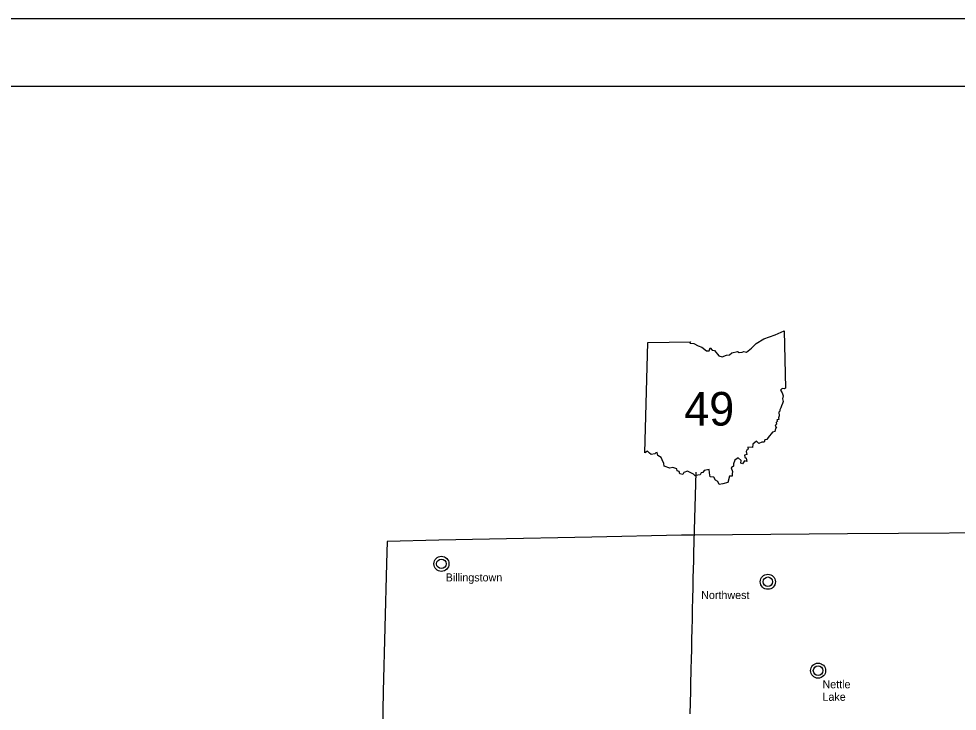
# Model space of a CAD drawing. Extents: x -66 to 795, y 0 to 440.
# Drawn here: x 111.4 to 250.6, y 337.3 to 440 of the extents above; entities that cross this region are included whole.
import ezdxf

# ---------------------------------------------------------------- set-up
doc = ezdxf.new("R2010")
doc.units = 0
for name, color, linetype in [('DV_X_Corp_Line', 7, 'Continuous'), ('GM_X_County', 7, 'Continuous'), ('GM_X_State_Route', 7, 'Continuous'), ('PV_P_Text', 7, 'Continuous'), ('SH_Border', 7, 'Continuous'), ('SH_Cut_Line', 7, 'Continuous')]:
    doc.layers.add(name, color=color, linetype=linetype)

msp = doc.modelspace()

# ---------------------------------------------------------------- linework, layer by layer
at = {"layer": 'DV_X_Corp_Line'}
for centre, radius in [((174.08, 359.17), 1.12), ((174.08, 359.17), 0.71), ((222.51, 356.51), 1.12), ((222.51, 356.51), 0.71), ((229.96, 343.33), 1.12), ((229.96, 343.33), 0.71)]:
    msp.add_circle(centre, radius, dxfattribs=at)
at = {"layer": 'GM_X_County'}
msp.add_lwpolyline([(256.96, 363.76), (241.88, 363.65), (234.32, 363.6), (211.6, 363.44), (209.69, 363.42), (196.42, 363.14), (181.24, 362.82), (173.68, 362.66), (166.04, 362.5), (165.94, 359.23), (165.44, 340.23), (165.03, 317.58)], dxfattribs=at)
at = {"layer": 'GM_X_State_Route'}
msp.add_lwpolyline([(210.98, 336.94), (211.03, 338.54), (211.07, 340.3), (211.09, 341.88), (211.11, 342.92), (211.14, 343.59), (211.18, 344.97), (211.21, 346.53), (211.24, 347.98), (211.28, 349.42), (211.31, 351.01), (211.35, 352.45), (211.38, 354.02), (211.42, 355.67), (211.45, 356.99), (211.48, 358.43), (211.49, 358.63), (211.51, 359.39), (211.54, 360.82), (211.57, 362.43), (211.85, 372.76)], dxfattribs=at)
at = {"layer": 'PV_P_Text'}
msp.add_line((204.24, 375.62), (204.7, 391.99), dxfattribs=at)
msp.add_line((204.24, 375.62), (204.7, 391.99), dxfattribs=at)
for points in [[(204.7, 391.99), (211.05, 392.1), (210.95, 391.9), (211.55, 391.86), (212.19, 391.51), (212.73, 391.29), (213.39, 390.77), (213.78, 390.77), (213.95, 391.2), (214.25, 390.87), (214.61, 390.81), (215.23, 390.03), (215.74, 389.86), (216.35, 390.13), (216.81, 390.17), (217.14, 390.44), (218.01, 390.66), (218.26, 390.53), (218.72, 390.55), (218.95, 390.65), (219.35, 390.56), (220.06, 391.16), (220.79, 391.86), (221.91, 392.52), (223.59, 393.15), (224.91, 393.71), (225.11, 385.22)], [(204.7, 391.99), (211.05, 392.1), (210.95, 391.9), (211.55, 391.86), (212.19, 391.51), (212.73, 391.29), (213.39, 390.77), (213.78, 390.77), (213.95, 391.2), (214.25, 390.87), (214.61, 390.81), (215.23, 390.03), (215.74, 389.86), (216.35, 390.13), (216.81, 390.17), (217.14, 390.44), (218.01, 390.66), (218.26, 390.53), (218.72, 390.55), (218.95, 390.65), (219.35, 390.56), (220.06, 391.16), (220.79, 391.86), (221.91, 392.52), (223.59, 393.15), (224.91, 393.71), (225.11, 385.22)], [(225.11, 385.22), (224.91, 385.1), (224.61, 385.15), (224.4, 384.91), (224.65, 384.52), (224.77, 384.1), (224.67, 383.63), (224.77, 383.25), (224.7, 382.93), (224.51, 382.61), (224.44, 382.31), (224.28, 381.99), (224.29, 381.81), (224.14, 381.67), (224.17, 381.14), (224.09, 380.84), (224.12, 380.59), (223.86, 380.52), (223.92, 380.31), (223.76, 380.15), (223.8, 379.87), (223.61, 379.7), (223.79, 379.34), (223.65, 379.23), (223.53, 378.79), (223.21, 378.7), (222.56, 377.91), (222.34, 377.61), (222.08, 377.54), (221.94, 377.23), (221.62, 377.23), (221.15, 377.01), (220.84, 377.38), (220.3, 376.94), (220.23, 376.43), (219.55, 376.45), (219.58, 376.19), (219.43, 376.11), (219.29, 375.85), (219.37, 375.39), (219.05, 375.28), (219.09, 375.01), (219.29, 374.85), (219.38, 374.34), (219.04, 374.44), (218.76, 374.01), (218.48, 374.11), (218.57, 374.48), (218.09, 374.91), (217.63, 374.56), (217.39, 374), (217.39, 373.63), (217.05, 373.4), (217.26, 372.87), (217.22, 372.5), (217.23, 372.15), (216.8, 372.16), (216.55, 371.22)], [(225.11, 385.22), (224.91, 385.1), (224.61, 385.15), (224.4, 384.91), (224.65, 384.52), (224.77, 384.1), (224.67, 383.63), (224.77, 383.25), (224.7, 382.93), (224.51, 382.61), (224.44, 382.31), (224.28, 381.99), (224.29, 381.81), (224.14, 381.67), (224.17, 381.14), (224.09, 380.84), (224.12, 380.59), (223.86, 380.52), (223.92, 380.31), (223.76, 380.15), (223.8, 379.87), (223.61, 379.7), (223.79, 379.34), (223.65, 379.23), (223.53, 378.79), (223.21, 378.7), (222.56, 377.91), (222.34, 377.61), (222.08, 377.54), (221.94, 377.23), (221.62, 377.23), (221.15, 377.01), (220.84, 377.38), (220.3, 376.94), (220.23, 376.43), (219.55, 376.45), (219.58, 376.19), (219.43, 376.11), (219.29, 375.85), (219.37, 375.39), (219.05, 375.28), (219.09, 375.01), (219.29, 374.85), (219.38, 374.34), (219.04, 374.44), (218.76, 374.01), (218.48, 374.11), (218.57, 374.48), (218.09, 374.91), (217.63, 374.56), (217.39, 374), (217.39, 373.63), (217.05, 373.4), (217.26, 372.87), (217.22, 372.5), (217.23, 372.15), (216.8, 372.16), (216.55, 371.22)], [(216.55, 371.22), (215.81, 371.04), (215.29, 370.94), (215.11, 371.36), (214.74, 371.59), (214.5, 372.02), (213.97, 372.08), (213.85, 372.67), (213.79, 373.15), (213.07, 373.03), (212.87, 372.73), (212.61, 372.66), (212.46, 372.36), (212.11, 372.34), (211.74, 372.2), (211.49, 372.49), (210.88, 372.78), (210.6, 372.93), (210.03, 372.69), (209.9, 372.42), (209.44, 372.54), (209.34, 372.85), (209.06, 372.94), (209, 373.27), (208.4, 373.44), (207.95, 373.37), (207.14, 373.63), (207.1, 374.06), (206.82, 374.58), (206.68, 374.95), (206.17, 375.22), (206.07, 375.66), (205.91, 375.64), (205.76, 375.47), (205.2, 375.39), (204.97, 375.56), (204.66, 375.87), (204.24, 375.62)], [(216.55, 371.22), (215.81, 371.04), (215.29, 370.94), (215.11, 371.36), (214.74, 371.59), (214.5, 372.02), (213.97, 372.08), (213.85, 372.67), (213.79, 373.15), (213.07, 373.03), (212.87, 372.73), (212.61, 372.66), (212.46, 372.36), (212.11, 372.34), (211.74, 372.2), (211.49, 372.49), (210.88, 372.78), (210.6, 372.93), (210.03, 372.69), (209.9, 372.42), (209.44, 372.54), (209.34, 372.85), (209.06, 372.94), (209, 373.27), (208.4, 373.44), (207.95, 373.37), (207.14, 373.63), (207.1, 374.06), (206.82, 374.58), (206.68, 374.95), (206.17, 375.22), (206.07, 375.66), (205.91, 375.64), (205.76, 375.47), (205.2, 375.39), (204.97, 375.56), (204.66, 375.87), (204.24, 375.62)]]:
    msp.add_lwpolyline(points, dxfattribs=at)
at = {"layer": 'SH_Border'}
msp.add_lwpolyline([(30, 430), (670, 430), (670, 10), (30, 10)], close=True, dxfattribs=at)
at = {"layer": 'SH_Cut_Line'}
msp.add_lwpolyline([(0, 0), (680, 0), (680, 440), (0, 440)], close=True, dxfattribs=at)

# ---------------------------------------------------------------- texts
at = {"layer": 'DV_X_Corp_Line'}
for s, height, p in [('Billingstown', 1.1875, (174.72, 356.56)), ('Northwest', 1.188, (212.62, 353.95)), ('Nettle', 1.188, (230.61, 340.72)), ('Lake', 1.188, (230.61, 338.86))]:
    msp.add_text(s, height=height, rotation=0, dxfattribs=at).set_placement(p)
at = {"layer": 'PV_P_Text'}
msp.add_text('49', height=4.987, dxfattribs=at).set_placement((210.1, 379.67))

doc.saveas('drawing.dxf')
